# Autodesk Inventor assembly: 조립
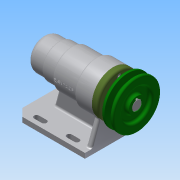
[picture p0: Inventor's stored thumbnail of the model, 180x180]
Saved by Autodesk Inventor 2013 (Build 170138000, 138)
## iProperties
Created: 2017-09
Part Number: 조립
Document SubType Name: Assembly
Designer: Administrator
Author: Administrator
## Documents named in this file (11)
- C:\Users\Administrator\Desktop\470908V1005\조립.iam
- C:\Users\Administrator\Desktop\470908V1005\본체.ipt
- C:\Users\Administrator\Desktop\470908V1005\축.ipt
- C:\Users\Administrator\Desktop\470908V1005\베어링 51202.ipt
- C:\Users\Administrator\Desktop\470908V1005\어댑터슬리브.ipt
- C:\Users\Administrator\Desktop\470908V1005\볼트 M4 x 12.ipt
- C:\Users\Administrator\Desktop\470908V1005\베어링 6004.ipt
- C:\Users\Administrator\Desktop\470908V1005\커버.ipt
- C:\Users\Administrator\Desktop\470908V1005\키 5 x 5 x 16.ipt
- C:\Users\Administrator\Desktop\470908V1005\V벨트풀리.ipt
- C:\Users\Administrator\Desktop\470908V1005\멈춤나사 M3x8.ipt
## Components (1 placed, 1 different names)
1. V벨트풀리:1 — 각도:1
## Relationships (1: Angle 1)
- 각도:1 [Angle]: V벨트풀리:1
